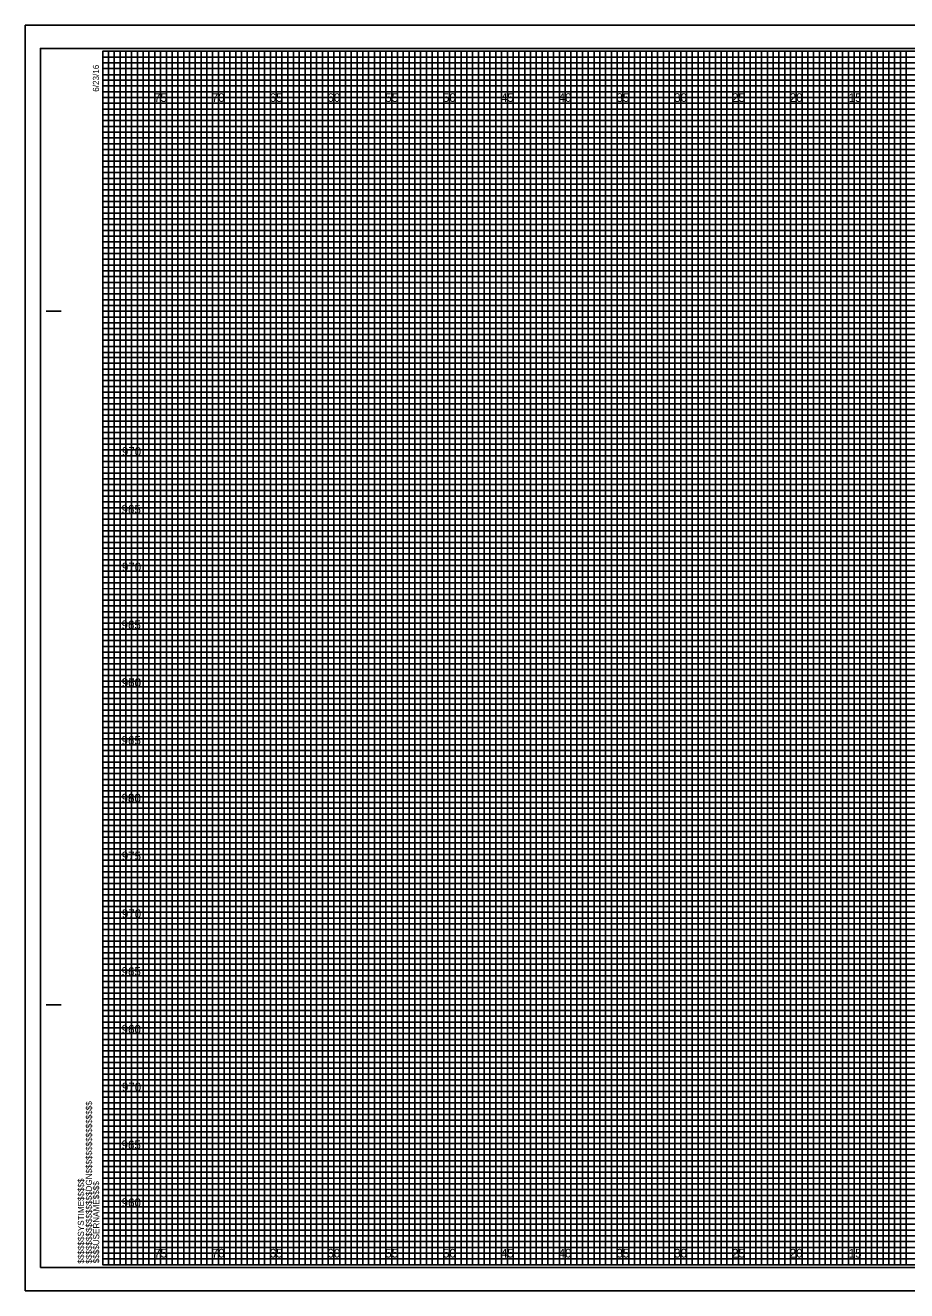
# Model space of a CAD drawing. Extents: x -7 to 162, y -2 to 107.
# Drawn here: x -6.7 to 69.5, y -2.3 to 107.3 of the extents above; entities that cross this region are included whole.
import ezdxf

# ---------------------------------------------------------------- set-up
doc = ezdxf.new("R2010")
doc.units = 0
for name, color, linetype in [('Prop XS Elevation Labels', 7, 'Continuous'), ('Prop XS Offset Labels', 7, 'Continuous'), ('Sheet Cross Section CELL', 7, 'Continuous'), ('Sheet Cross Section Grid Major CELL', 7, 'Continuous'), ('Sheet Cross Section Grid Middle CELL', 7, 'Continuous'), ('Sheet Cross Section Grid Minor 1 CELL', 7, 'Continuous'), ('Sheet Cross Section Grid Minor 2 CELL', 7, 'Continuous'), ('Sheet Cutting Line CELL', 7, 'Continuous'), ('Sheet DOT Grid CELL', 7, 'Continuous'), ('Sheet Plot Border Inside CELL', 7, 'Continuous'), ('Sheet Plot Border Outside CELL', 7, 'Continuous')]:
    doc.layers.add(name, color=color, linetype=linetype)

msp = doc.modelspace()

# ---------------------------------------------------------------- linework, layer by layer
at = {"layer": 'Sheet Cross Section CELL'}
for p, q in [((-4.9, 82.5), (-3.65, 82.5)), ((-4.85, 82.5), (-3.6, 82.5)), ((-4.9, 22.5), (-3.65, 22.5)), ((-4.85, 22.5), (-3.6, 22.5)), ((0, 0), (0, 0)), ((0, 0), (0, 0)), ((0, 0), (0, 0)), ((0, 0), (0, 0)), ((0, 0), (0, 0)), ((0, 0), (0, 0)), ((0, 0), (0, 0))]:
    msp.add_line(p, q, dxfattribs=at)
msp.add_lwpolyline([(160, 105), (0, 105), (0, 0), (160, 0)], close=True, dxfattribs=at)
at = {"layer": 'Sheet Cross Section Grid Major CELL'}
for p, q in [((5, 105), (0, 105)), ((5, 0), (5, 105)), ((15, 105), (10, 105)), ((10, 105), (10, 0)), ((15, 0), (15, 105)), ((25, 105), (20, 105)), ((20, 105), (20, 0)), ((25, 0), (25, 105)), ((35, 105), (30, 105)), ((30, 105), (30, 0)), ((35, 0), (35, 105)), ((45, 105), (40, 105)), ((40, 105), (40, 0)), ((45, 0), (45, 105)), ((55, 105), (50, 105)), ((50, 105), (50, 0)), ((55, 0), (55, 105)), ((65, 105), (60, 105)), ((60, 105), (60, 0)), ((65, 0), (65, 105)), ((10, 0), (5, 0)), ((20, 0), (15, 0)), ((30, 0), (25, 0)), ((40, 0), (35, 0)), ((50, 0), (45, 0)), ((60, 0), (55, 0)), ((70, 0), (65, 0))]:
    msp.add_line(p, q, dxfattribs=at)
for points in [[(0, 100), (160, 100), (160, 95), (0, 95)], [(0, 90), (160, 90), (160, 85), (0, 85)], [(0, 80), (160, 80), (160, 75), (0, 75)], [(0, 70), (160, 70), (160, 65), (0, 65)], [(0, 60), (160, 60), (160, 55), (0, 55)], [(0, 50), (160, 50), (160, 45), (0, 45)], [(0, 40), (160, 40), (160, 35), (0, 35)], [(0, 30), (160, 30), (160, 25), (0, 25)], [(0, 20), (160, 20), (160, 15), (0, 15)], [(0, 10), (160, 10), (160, 5), (0, 5)]]:
    msp.add_lwpolyline(points, dxfattribs=at)
at = {"layer": 'Sheet Cross Section Grid Middle CELL'}
for points in [[(0, 105), (2.5, 105), (2.5, 0), (7.5, 0), (7.5, 105), (12.5, 105), (12.5, 0), (17.5, 0), (17.5, 105), (22.5, 105), (22.5, 0), (27.5, 0), (27.5, 105), (32.5, 105), (32.5, 0), (37.5, 0), (37.5, 105), (42.5, 105), (42.5, 0), (47.5, 0), (47.5, 105), (52.5, 105), (52.5, 0), (57.5, 0), (57.5, 105), (62.5, 105), (62.5, 0), (67.5, 0), (67.5, 105), (72.5, 105)], [(0, 102.5), (137.5, 102.5)], [(0, 92.5), (160, 92.5), (160, 97.5), (0, 97.5)], [(0, 82.5), (160, 82.5), (160, 87.5), (0, 87.5)], [(0, 72.5), (160, 72.5), (160, 77.5), (0, 77.5)], [(0, 62.5), (160, 62.5), (160, 67.5), (0, 67.5)], [(0, 52.5), (160, 52.5), (160, 57.5), (0, 57.5)], [(0, 42.5), (160, 42.5), (160, 47.5), (0, 47.5)], [(0, 32.5), (160, 32.5), (160, 37.5), (0, 37.5)], [(0, 22.5), (160, 22.5), (160, 27.5), (0, 27.5)], [(0, 12.5), (160, 12.5), (160, 17.5), (0, 17.5)], [(0, 2.5), (160, 2.5), (160, 7.5), (0, 7.5)]]:
    msp.add_lwpolyline(points, dxfattribs=at)
at = {"layer": 'Sheet Cross Section Grid Minor 1 CELL'}
for p, q in [((0, 104.5), (130, 104.5)), ((130, 103.99), (0, 103.99)), ((0, 103.99), (0, 103.5)), ((0, 103.5), (130, 103.5)), ((130, 102.95), (0, 102.95)), ((0, 102.95), (0, 102)), ((0, 102), (160, 102))]:
    msp.add_line(p, q, dxfattribs=at)
for points in [[(0, 101.5), (135, 101.5), (160, 101.5), (160, 101), (0, 101)], [(0, 100.5), (160, 100.5), (160, 99.5), (0, 99.5)], [(0, 99), (160, 99), (160, 98.5), (0, 98.49)], [(0, 98), (160, 98), (160, 97), (0, 97)], [(0, 96.5), (160, 96.5), (160, 96), (0, 96)], [(0, 95.5), (160, 95.5), (160, 94.5), (0, 94.5)], [(0, 94), (160, 94), (160, 93.5), (0, 93.5)], [(0, 93), (160, 93), (160, 92), (0, 92)], [(0, 91.5), (160, 91.5), (160, 91), (0, 91)], [(0, 90.5), (160, 90.5), (160, 89.5), (0, 89.5)], [(0, 89), (160, 89), (160, 88.5), (0, 88.5)], [(0, 88), (160, 88), (160, 86.98), (160, 86.5), (160, 86), (0, 86)], [(0, 87), (160, 87), (160, 86.5), (0, 86.5)], [(0, 85.5), (160, 85.5), (160, 84.5), (0, 84.52)], [(0, 84.52), (160, 84.5), (160, 84), (0, 84)], [(0, 83.5), (160, 83.5), (160, 83), (0, 83)], [(0, 82), (160, 82), (160, 81.5), (0, 81.5)], [(0, 81), (160, 81), (160, 80.5), (0, 80.5)], [(-0.04, 79.45), (160, 79.45), (160, 78.94), (-0.04, 78.94)], [(0, 78.5), (160, 78.5), (160, 78), (0, 78)], [(0, 77), (160, 77), (160, 76.5), (0, 76.5)], [(0, 76), (160, 76), (160, 75.5), (0, 75.5)], [(0, 74.5), (160, 74.5), (160, 74), (0, 74)], [(0, 73.5), (160, 73.5), (160, 73), (0, 73)], [(0, 72), (160, 72), (160, 71.5), (0, 71.5)], [(0, 71), (160, 71), (160, 70.5), (0, 70.5)], [(0, 69.5), (160, 69.5), (160, 68.99), (0, 69)], [(0, 68.5), (160, 68.5), (160, 68), (0, 68)], [(0, 67), (160, 67), (160, 66.5), (0, 66.5)], [(0, 66), (160, 66), (160, 65.5), (0, 65.5)], [(0, 64.5), (160, 64.5), (160, 64), (0, 64)], [(0, 63.5), (160, 63.5), (160, 63), (0, 63)], [(0, 62), (160, 62), (160, 61.5), (0, 61.5)], [(0, 61), (160, 61), (160, 60.5), (0, 60.5)], [(0, 59.5), (160, 59.5), (160, 59), (0, 59)], [(0, 58.5), (160.03, 58.45), (160, 58), (0, 58)], [(0, 57), (160, 57), (160, 56.5), (0, 56.5)], [(0, 56), (160, 56), (160, 55.5), (0, 55.5)], [(0, 54.5), (160, 54.5), (160, 54), (0, 54)], [(0, 53.5), (160, 53.5), (160, 53), (0, 53)], [(0, 52), (160, 52), (160, 51.5), (0, 51.5)], [(0, 51), (160, 51), (160, 50.5), (0, 50.5)], [(0, 49.5), (160, 49.5), (160, 49), (0, 49)], [(0, 48.5), (160, 48.5), (160, 48), (0, 48)], [(0, 47), (160, 47), (160, 46.5), (0, 46.5)], [(0, 46), (160, 46), (160, 45.5), (0, 45.5)], [(0, 44.5), (160, 44.5), (160, 44), (0, 44)], [(0, 43.5), (160, 43.5), (160, 43), (0, 43)], [(0, 42), (160, 42), (160, 41.5), (0, 41.5)], [(0, 41), (160, 41), (160, 40.5), (0, 40.5)], [(0, 39.5), (160, 39.5), (160, 38.99), (0, 39)], [(0, 38.5), (160, 38.5), (160, 38), (0, 38)], [(0, 37), (160, 37), (160, 36.5), (0, 36.5)], [(0, 36), (160, 36), (160, 35.5), (0, 35.5)], [(0, 34.5), (160, 34.5), (160, 34), (0, 34)], [(0, 33.5), (160, 33.5), (160, 33), (0, 33)], [(0, 32), (160, 32), (160, 31.5), (0, 31.5)], [(0, 31), (160, 31), (160, 30.5), (0, 30.5)], [(0, 29.5), (160, 29.5), (160, 29), (0, 29)], [(0, 28.5), (160.03, 28.46), (160, 28), (0, 28)], [(0, 27), (160, 27), (160, 26.5), (0, 26.5)], [(0, 26), (160, 26), (160, 25.5), (0, 25.5)], [(0, 24.5), (160, 24.5), (160, 24), (0, 24)], [(0, 23.5), (160, 23.5), (160, 23), (0, 23)], [(0, 22), (160, 22), (160, 21.5), (0, 21.5)], [(0, 21), (160, 21), (160, 20.5), (0, 20.5)], [(0, 19.5), (160, 19.5), (160, 19), (0, 19)], [(0, 18.5), (160, 18.5), (160, 18), (0, 18)], [(0, 17), (160, 17), (160, 16.5), (0, 16.5)], [(0, 16), (160, 16), (160, 15.5), (0, 15.5)], [(0, 14.5), (160, 14.5), (160, 14), (0, 14)], [(0, 13.5), (160, 13.5), (160, 13), (0, 13)], [(0, 12), (160, 12), (160, 11.5), (0, 11.5)], [(0, 11), (160, 11), (160, 10.5), (0, 10.5)], [(0, 9.5), (160, 9.5), (160, 9), (0, 9)], [(0, 8.5), (160, 8.5), (160, 8), (0, 8)], [(0, 7), (160, 7), (160, 6.5), (0, 6.5)], [(0, 6), (160, 6), (160, 5.5), (0, 5.5)], [(0, 4.5), (160, 4.5), (160, 4), (0, 4)], [(0, 3.5), (160, 3.5), (160, 3), (0, 3)], [(0, 2), (160, 2), (160, 1.5), (0, 1.5)], [(0, 1), (160, 1), (160, 0.5), (0, 0.5)]]:
    msp.add_lwpolyline(points, dxfattribs=at)
at = {"layer": 'Sheet Cross Section Grid Minor 2 CELL'}
for points in [[(0, 0), (0.5, 0), (0.5, 105), (1, 105), (1, 0)], [(1, 0), (1.5, 0), (1.5, 105), (2, 105), (2, 0)], [(2.5, 0), (3, 0), (3, 105), (3.5, 105), (3.5, 0)], [(3.5, 0), (4, 0), (4, 105), (4.5, 105), (4.5, 0)], [(5, 0), (5.5, 0), (5.5, 105), (6, 105), (6, 0)], [(6, 0), (6.5, 0), (6.5, 105), (7, 105), (7, 0)], [(7.5, 0), (8, 0), (8, 105), (8.5, 105), (8.5, 0)], [(8.5, 0), (9, 0), (9, 105), (9.5, 105), (9.5, 0)], [(10, 0), (10.5, 0), (10.5, 105), (11, 105), (11, 0)], [(11, 0), (11.5, 0), (11.5, 105), (12, 105), (12, 0)], [(12.5, 0), (13, 0), (13, 105), (13.5, 105), (13.5, 0)], [(13.5, 0), (14, 0), (14, 105), (14.5, 105), (14.5, 0)], [(15, 0), (15.5, 0), (15.5, 105), (16, 105), (16, 0)], [(16, 0), (16.5, 0), (16.5, 105), (17, 105), (17, 0)], [(17.5, 0), (18, 0), (18, 105), (18.5, 105), (18.5, 0)], [(18.5, 0), (19, 0), (19, 105), (19.5, 105), (19.5, 0)], [(20, 0), (20.5, 0), (20.5, 105), (21, 105), (21, 0)], [(21, 0), (21.5, 0), (21.5, 105), (22, 105), (22, 0)], [(22.5, 0), (23, 0), (23, 105), (23.5, 105), (23.5, 0)], [(23.5, 0), (24, 0), (24, 105), (24.5, 105), (24.5, 0)], [(25, 0), (25.5, 0), (25.5, 105), (26, 105), (26, 0)], [(26, 0), (26.5, 0), (26.5, 105), (27, 105), (27, 0)], [(27.5, 0), (28, 0), (28, 105), (28.5, 105), (28.5, 0)], [(28.5, 0), (29, 0), (29, 105), (29.5, 105), (29.5, 0)], [(30, 0), (30.5, 0), (30.5, 105), (31, 105), (31, 0)], [(31, 0), (31.5, 0), (31.5, 105), (32, 105), (32, 0)], [(32.5, 0), (33, 0), (33, 105), (33.5, 105), (33.5, 0)], [(33.5, 0), (34, 0), (34, 105), (34.5, 105), (34.5, 0)], [(35, 0), (35.5, 0), (35.5, 105), (36, 105), (36, 0)], [(36, 0), (36.5, 0), (36.5, 105), (37, 105), (37, 0)], [(37.5, 0), (38, 0), (38, 105), (38.5, 105), (38.5, 0)], [(38.5, 0), (39, 0), (39, 105), (39.5, 105), (39.5, 0)], [(40, 0), (40.5, 0), (40.5, 105), (41, 105), (41, 0)], [(41, 0), (41.5, 0), (41.5, 105), (42, 105), (42, 0)], [(42.5, 0), (43, 0), (43, 105), (43.5, 105), (43.5, 0)], [(43.5, 0), (44, 0), (44, 105), (44.5, 105), (44.5, 0)], [(45, 0), (45.5, 0), (45.5, 105), (46, 105), (46, 0)], [(46, 0), (46.5, 0), (46.5, 105), (47, 105), (47, 0)], [(47.5, 0), (48, 0), (48, 105), (48.5, 105), (48.5, 0)], [(48.5, 0), (49, 0), (49, 105), (49.5, 105), (49.5, 0)], [(50, 0), (50.5, 0), (50.5, 105), (51, 105), (51, 0)], [(51, 0), (51.5, 0), (51.5, 105), (52, 105), (52, 0)], [(52.5, 0), (53, 0), (53, 105), (53.5, 105), (53.5, 0)], [(53.5, 0), (54, 0), (54, 105), (54.5, 105), (54.5, 0)], [(55, 0), (55.5, 0), (55.5, 105), (56, 105), (56, 0)], [(56, 0), (56.5, 0), (56.5, 105), (57, 105), (57, 0)], [(57.5, 0), (58, 0), (58, 105), (58.5, 105), (58.5, 0)], [(58.5, 0), (59, 0), (59, 105), (59.5, 105), (59.5, 0)], [(60, 0), (60.5, 0), (60.5, 105), (61, 105), (61, 0)], [(61, 0), (61.5, 0), (61.5, 105), (62, 105), (62, 0)], [(62.5, 0), (63, 0), (63, 105), (63.5, 105), (63.5, 0)], [(63.5, 0), (64, 0), (64, 105), (64.5, 105), (64.5, 0)], [(65, 0), (65.5, 0), (65.5, 105), (66, 105), (66, 0)], [(66, 0), (66.5, 0), (66.5, 105), (67, 105), (67, 0)], [(67.5, 0), (68, 0), (68, 105), (68.5, 105), (68.5, 0)], [(68.5, 0), (69, 0), (69, 105), (69.5, 105), (69.5, 0)]]:
    msp.add_lwpolyline(points, dxfattribs=at)
at = {"layer": 'Sheet Cutting Line CELL'}
for p, q in [((161.65, 107.25), (-6.7, 107.25)), ((-6.7, 107.25), (-6.7, -2.25)), ((-6.7, -2.25), (161.65, -2.25))]:
    msp.add_line(p, q, dxfattribs=at)
at = {"layer": 'Sheet DOT Grid CELL'}
for p, q in [((5, 0), (5, 105)), ((10, 0), (10, 105)), ((15, 0), (15, 105)), ((20, 0), (20, 105)), ((25, 0), (25, 105)), ((30, 0), (30, 105)), ((35, 0), (35, 105)), ((40, 0), (40, 105)), ((45, 0), (45, 105)), ((50, 0), (50, 105)), ((55, 0), (55, 105)), ((60, 0), (60, 105)), ((65, 0), (65, 105)), ((0, 100), (160, 100)), ((0, 95), (160, 95)), ((0, 90), (160, 90)), ((0, 85), (160, 85)), ((0, 80), (160, 80)), ((0, 75), (160, 75)), ((0, 70), (160, 70)), ((0, 65), (160, 65)), ((0, 60), (160, 60)), ((0, 55), (160, 55)), ((0, 50), (160, 50)), ((0, 45), (160, 45)), ((0, 40), (160, 40)), ((0, 35), (160, 35)), ((0, 30), (160, 30)), ((0, 25), (160, 25)), ((0, 20), (160, 20)), ((0, 15), (160, 15)), ((0, 10), (160, 10)), ((0, 5), (160, 5))]:
    msp.add_line(p, q, dxfattribs=at)
at = {"layer": 'Sheet Plot Border Inside CELL'}
msp.add_lwpolyline([(-5.4, -0.25), (161.2, -0.25), (161.2, 105.25), (-5.4, 105.25)], close=True, dxfattribs=at)
at = {"layer": 'Sheet Plot Border Outside CELL'}
msp.add_lwpolyline([(-6.7, -2.25), (161.65, -2.25), (161.65, 107.25), (-6.7, 107.25)], close=True, dxfattribs=at)

# ---------------------------------------------------------------- texts
at = {"layer": 'Prop XS Elevation Labels'}
for s, p in [('970', (1.65, 70)), ('965', (1.62, 65)), ('970', (1.65, 60)), ('965', (1.62, 55)), ('960', (1.63, 50)), ('970', (1.65, 50)), ('965', (1.62, 45)), ('980', (1.62, 40)), ('960', (1.63, 40)), ('975', (1.64, 35)), ('970', (1.65, 30)), ('965', (1.62, 25)), ('960', (1.63, 20)), ('970', (1.65, 15)), ('965', (1.62, 10)), ('960', (1.63, 5))]:
    msp.add_text(s, height=0.75, dxfattribs=at).set_placement(p)
at = {"layer": 'Prop XS Offset Labels'}
for s, p in [('75', (4.44, 100.62)), ('70', (9.43, 100.62)), ('65', (14.44, 100.62)), ('60', (19.43, 100.62)), ('55', (24.44, 100.62)), ('50', (29.43, 100.62)), ('45', (34.44, 100.62)), ('40', (39.43, 100.62)), ('35', (44.44, 100.62)), ('30', (49.43, 100.62)), ('25', (54.44, 100.62)), ('20', (59.43, 100.62)), ('15', (64.53, 100.62)), ('75', (4.44, 0.62)), ('70', (9.43, 0.62)), ('65', (14.44, 0.62)), ('60', (19.43, 0.62)), ('55', (24.44, 0.62)), ('50', (29.43, 0.62)), ('45', (34.44, 0.62)), ('40', (39.43, 0.62)), ('35', (44.44, 0.62)), ('30', (49.43, 0.62)), ('25', (54.44, 0.62)), ('20', (59.43, 0.62)), ('15', (64.53, 0.62))]:
    msp.add_text(s, height=0.75, dxfattribs=at).set_placement(p)
at = {"layer": 'Sheet Cross Section CELL'}
for s, p in [('6/23/16', (-0.33, 101.5)), ('$$$$$$$$$$$$$$$$DGN$$$$$$$$$$$$$$$$', (-0.94, 0.09)), ('$$$$$$SYSTIME$$$$$', (-1.63, 0.09)), ('$$$$USERNAME$$$$', (-0.31, 0.12))]:
    msp.add_text(s, height=0.525, rotation=90, dxfattribs=at).set_placement(p)

doc.saveas('drawing.dxf')
